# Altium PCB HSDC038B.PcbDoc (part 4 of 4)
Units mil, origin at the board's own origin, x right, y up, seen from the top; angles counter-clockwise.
Board outline 3620 x 4060 mil, 6 copper layers (Top Layer, Signal Layer 1, Signal Layer 2, Signal Layer 3, Signal Layer 4, Bottom Layer), stack 60.4 mil thick; 349 components, 209 nets, 1023 pads, 960 vias.
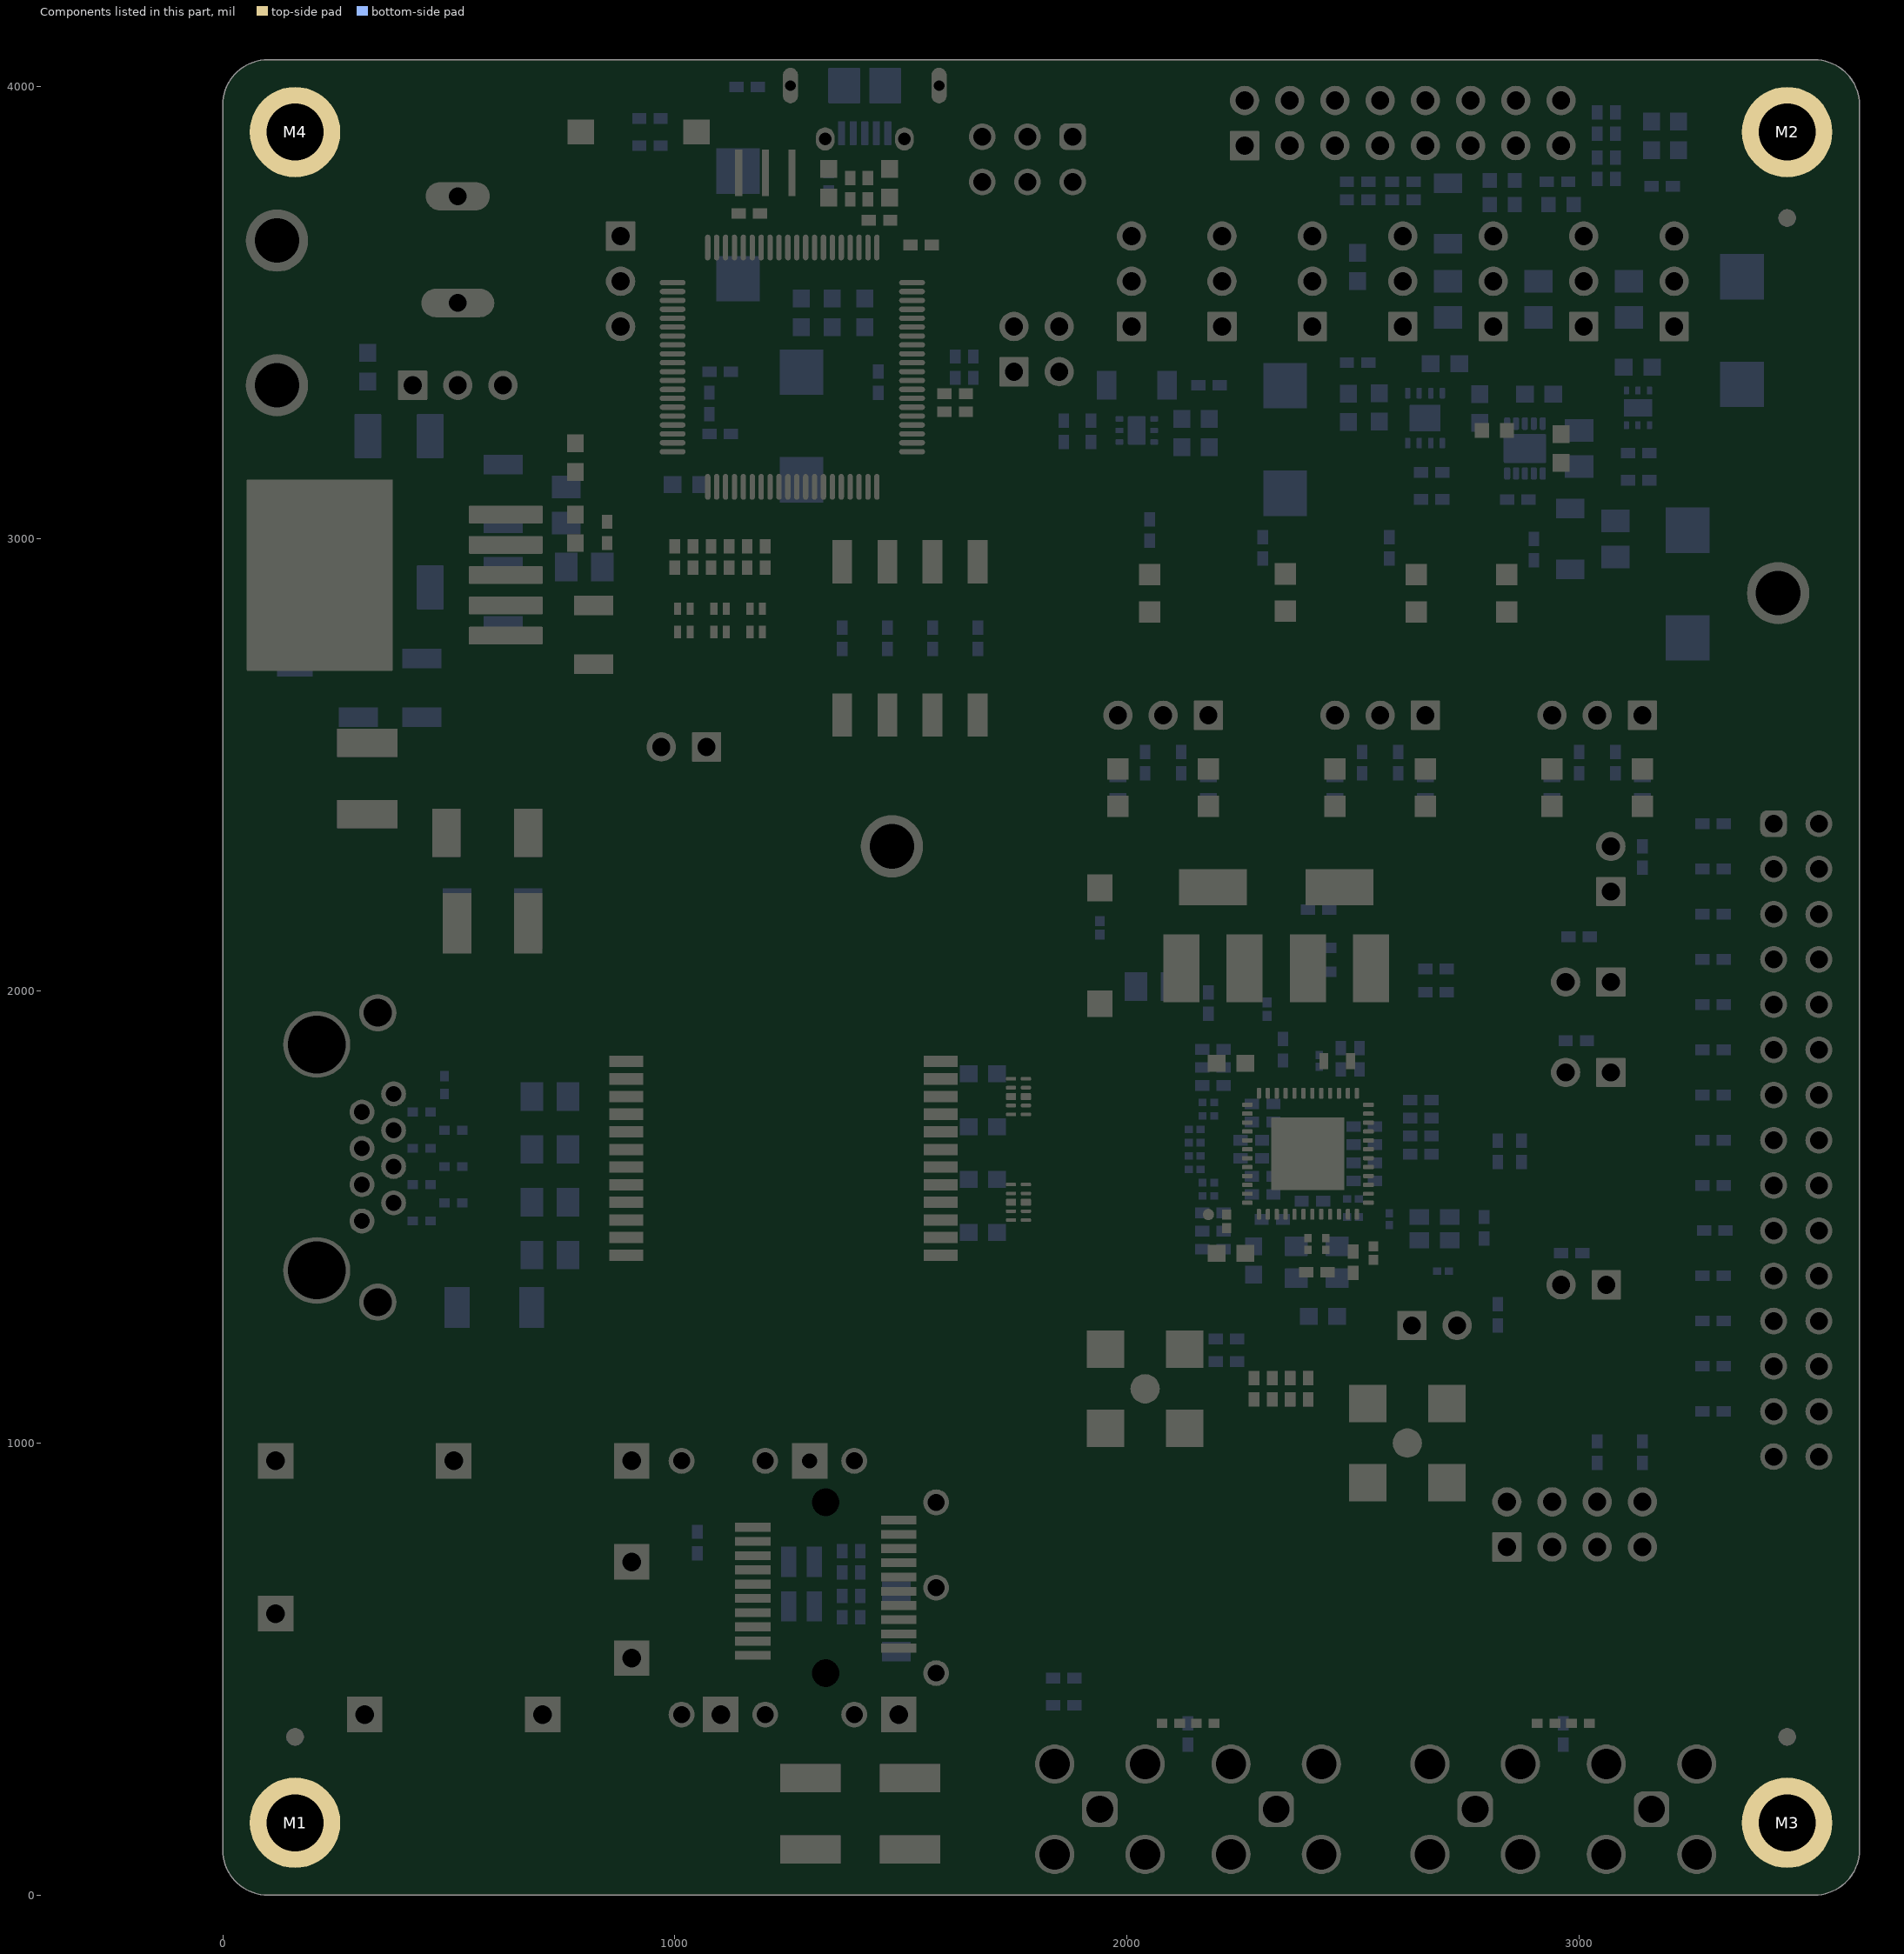
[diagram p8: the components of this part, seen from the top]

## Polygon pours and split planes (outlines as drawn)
EARTH_GND on Signal Layer 2 "Signal Layer 2-Earth GND" (solid, remove dead copper, pour order 84): 0,2420 550,2420 550,1900 830,1900 830,1355 550,1355 550,1000 940,1000 940,360 550,360 550,0 0,0
AUX_IOVDD on Signal Layer 2 "AUX_IOVDD_L03_P081" (solid, remove dead copper, pour order 81): 800,0 3620,0 3620,4060 2000,4060 2000,3340 3340,3340 3340,2920 3040,2920 2940,3020 2800,3020 2700,2920 1540,2920 1540,2460 900,2460 900,1980 1640,1980 1640,1280 900,1280 900,1180 1800,1180 1800,140 800,140
5V_SUPPLY on Signal Layer 2 "5V_SUPPLY_L03_P080" (solid, remove dead copper, pour order 80): 3320,2940 3320,3320 1440,3320 1040,3720 800,3720 800,3420 1040,3420 1520,2940 2700,2940 2800,3040 2940,3040 3040,2940
VFX on Signal Layer 2 "VFX_L03_P079" (solid, remove dead copper, pour order 79): 1520,2480 1520,2920 1040,3400 780,3400 780,3740 1040,3740 1440,3340 1980,3340 1980,4060 0,4060 0,2580 900,2580 900,2480
GND on Top Layer "Top Layer-GND Net" (solid, remove dead copper, pour order 77): 800,0 3620,0 3620,4060 0,4060 0,2580 900,2580 900,1980 1640,1980 1640,1280 900,1280 900,1180 1800,1180 1800,140 800,140
EARTH_GND on Top Layer "Top Layer- ERTH GND" (solid, remove dead copper, pour order 78): 0,2420 549.99,2420 549.99,1975 435,1975 245,1785 245,1480 370,1355 549.99,1355 549.99,1000 1600,1000 1600,230 549.99,230 549.99,0 0,0
5V_LDO on Top Layer "5V_LDO_L01_P076" (solid, remove dead copper, pour order 76): 540,3015 540,2960 870,2960 870,3015
EARTH_GND on Signal Layer 3 "Signal Layer 3-Earth GND" (solid, remove dead copper, pour order 94): 0,2420 549.96,2420 549.96,1900 830,1900 830,1355 549.96,1355 549.96,1000 940,1000 940,360 549.96,360 549.96,0 0,0
20V-5V on Signal Layer 3 "20V-5V_L04_P090" (solid, remove dead copper, pour order 90): 0,2580 900,2580 900,2480 1240,2480 1240,2660 960,2940 680,2940 680,4060 0,4060
5V_LDO on Signal Layer 3 "5V_LDO_L04_P085" (solid, remove dead copper, pour order 85): 700,2960 940,2960 940,3520 700,3520
MCU_VBUS on Signal Layer 3 "MCU_VBUS_L04_P086" (solid, remove dead copper, pour order 86): 2040,3620 2040,3000 2020,2980 1880,2980 1880,3140 1520,3500 1340,3500 1340,3620
MCU_VCC on Signal Layer 3 "MCU_VCC_L04_P089" (solid, remove dead copper, pour order 89): 2060,3620 2240,3620 2240,3020 2020,2800 1740,2800 1740,2680 1240,2680 960,2960 960,3540 700,3540 700,4060 1320,4060 1320,3480 1520,3480 1860,3140 1860,2960 2020,2960 2060,3000
FX3V3 on Signal Layer 3 "FX3V3_L04_P087" (solid, remove dead copper, pour order 87): 2260,3620 2440,3620 2440,3010 1900,2470 1900,1380 2260,1380 2260,0 800,0 800,140 1180,140 1180,330 1500,330 1500,140 1800,140 1800,930 1520,930 1520,800 1290,570 1230,570 1230,810 1370,810 1450,890 1450,1180 900,1180 900,1280 1640,1280 1640,1980 900,1980 900,2460 1260,2460 1260,2660 1760,2660 1760,2780 2020,2780 2260,3020
VDDA2P5 on Signal Layer 3 "VDDA2P5_L04_P091" (solid, remove dead copper, pour order 91): 2660,3620 2840,3620 2840,2630 2370,2160 2370,1840 2260,1730 2260,1680 2200,1680 2200,1620 2260,1620 2260,1460 2260,1400 2180,1400 2180,1420 2130,1460 2130,1780 2160,1810 2160,1860 2080,1940 2080,2240 2660,2820
VDDA1P8_EXT on Signal Layer 3 "VDDA1P8_EXT_L04_P088" (solid, remove dead copper, pour order 88): 2460,3760 2510,3810 2510,3920 2640,3920 2640,2820 2070,2250 2070,1940 2150,1860 2150,1810 2120,1780 2120,1460 2160,1420 2160,1400 1920,1400 1920,2470 2460,3010
VDDA1P0 on Signal Layer 3 "VDDA1P0_L04_P092" (solid, remove dead copper, pour order 92): 2860,3620 3040,3620 3040,2580 2510,2050 2510,1830 2600,1740 2600,1642 2312,1642 2300,1630 2210,1630 2210,1670 2270,1670 2270,1720 2380,1830 2380,2150 2860,2630
VDDIO on Signal Layer 3 "VDDIO_L04_P093" (solid, remove dead copper, pour order 93): 1340,4060 3620,4060 3620,0 2280,0 2280,1600 2280,1620 2300,1620 2318,1638 2610,1638 2610,1750 2520,1840 2520,2040 3060,2580 3060,3640 1340,3640
EARTH_GND on Signal Layer 1 "Signal Layer 1- ERTH GND" (solid, remove dead copper, pour order 82): 0,2420 550,2420 550,1900 830,1900 830,1355 550,1355 550,1000 1600,1000 1600,230 550,230 550,0 0,0
GND on Signal Layer 1 "Signal Layer 1-GND Net" (solid, remove dead copper, pour order 83): 800,0 3620,0 3620,4060 0,4060 0,2580 900,2580 900,1980 1640,1980 1640,1280 900,1280 900,1180 1800,1180 1800,140 800,140
GND on Bottom Layer "Bottom Layer-GND Net" (solid, remove dead copper, pour order 115): 800,0 3620,0 3620,4060 0,4060 0,2580 900,2580 900,1980 1640,1980 1640,1280 900,1280 900,1180 1800,1180 1800,140 800,140
VDDIO_DUT on Bottom Layer "VDDIO_DUT_L06_P114" (solid, remove dead copper, pour order 114): 3050,3510 3050,3430 3070,3410 3130,3410 3130,3310 3070,3310 2970,3410 2970,3510
VDDA1P0_DUT on Bottom Layer "VDDA1P0_DUT_L06_P113" (solid, remove dead copper, pour order 113): 2770,3510 2770,3430 2889.91,3310.09 2889.91,3240 2967.62,3240 2970,3237.62 2970,3375 2935.39,3409.61 2890.39,3409.61 2850,3450 2850,3510
5V_SUPPLY on Bottom Layer "5V_SUPPLY_L06_P112" (solid, remove dead copper, pour order 112): 2850,3080 2930,3000 3130,3000 3170,2960 3300,2960 3300,3080 3160,3080 3130,3110 3130,3270 3050,3270 3050,3200 2940,3200 2940,3160 2850,3160
VDDA_3V3_DUT on Bottom Layer "VDDA_3V3_DUT_L06_P111" (solid, remove dead copper, pour order 111): 2450,3510 2450,3420 2290,3420 2240,3370 2200,3370 2180,3350 2180,3330 2210,3300 2210,3240 2050.68,3240 2050.68,3510
VDDA2P5_DUT on Bottom Layer "VDDA2P5_DUT_L06_P110" (solid, remove dead copper, pour order 110): 2650,3510 2650,3300 2538,3300 2538,3348 2570,3380 2570,3510
NetC98_1 on Bottom Layer "NETC98_1_L06_P109" (solid, remove dead copper, pour order 109): 2300,3280 2510,3280 2510,3410 2300,3410
NetC110_1 on Bottom Layer "NETC110_1_L06_P108" (solid, remove dead copper, pour order 108): 2840,3810 2950,3810 2950,3540 2870,3540 2870,3680 2840,3710
EARTH_GND on Bottom Layer "Bottom Layer- ERTH GND" (solid, remove dead copper, pour order 116): 0,2420 549.99,2420 549.99,1975 435,1975 245,1785 245,1480 370,1355 549.99,1355 549.99,1000 1600,1000 1600,230 549.99,230 549.99,0 0,0
5V_SUPPLY on Bottom Layer "5V_SUPPLY_L06_P100" (solid, remove dead copper, pour order 100): 1845,3280 1845,3245 1995,3245 1995,3280
5V_SUPPLY on Bottom Layer "5V_SUPPLY_L06_P102" (solid, remove dead copper, pour order 102): 2670,3070 2670,3230 2610,3230 2610,3070
VDDA1P0 on Bottom Layer "VDDA1P0_L06_P098" (solid, remove dead copper, pour order 98): 2875,3520 2875,3435 2945,3435 2945,3520
NetJ32_6 on Bottom Layer "NETJ32_6_L06_P104" (solid, remove dead copper, pour order 104): 1605,4060 1605,3955 1540,3955 1540,3855 1485,3855 1485,3955 1355,3955 1355,3855 1305,3855 1305,3955 1165,3955 1165,4060
5V_LDO on Bottom Layer "5V_LDO_L06_P099" (solid, remove dead copper, pour order 99): 570,3065 570,2900 800,2900 800,2975 850,2975 850,3015 800,3065
VDDA1P8_EXT on Bottom Layer "VDDA1P8_EXT_L06_P097" (solid, remove dead copper, pour order 97): 2510,3910 2610,3910 2610,3730 2510,3730
VDDIO on Bottom Layer "VDDIO_L06_P103" (solid, remove dead copper, pour order 103): 3070,3520 3070,3430 3250,3430 3250,3520
VDDA2P5 on Bottom Layer "VDDA2P5_L06_P105" (solid, remove dead copper, pour order 105): 2675,3520 2675,3435 2745,3435 2745,3520
AUX_IOVDD_EXT on Bottom Layer "AUX_IOVDD_EXT_L06_P106" (solid, remove dead copper, pour order 106): 2920,3820 2920,3920 3100,3920 3100,3820
EARTH_GND on Signal Layer 4 "Signal Layer 1-Earth GND" (solid, remove dead copper, pour order 96): 0,2420 550,2420 550,1900 830,1900 830,1355 550,1355 550,1000 960,1000 960,360 550,360 550,0 0,0
GND on Signal Layer 4 "Signal Layer 1-GND Net" (solid, remove dead copper, pour order 95): 800,0 3620,0 3620,4060 0,4060 0,2580 900,2580 900,1980 1640,1980 1640,1280 900,1280 900,1180 1800,1180 1800,880 1730,810 1565,810 1545,830 1180,830 1180,720 1540,720 1560,740 1760,740 1760,620 1565,620 1535,650 1180,650 1180,530 1540,530 1560,550 1800,550 1800,140 800,140

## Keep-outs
Keep-Out Layer:
  lines w10: -5,100 ccw(c100,100) 100,-5 3520,-5 ccw(c3520,100) 3625,100 3625,3960 ccw(c3520,3960) 3520,4065 100,4065 ccw(c100,3960) -5,3960 -5,100

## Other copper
Top Layer:
  pour cut-out: 960,440 960,920 1560,920 1560,440
  pour cut-out: 2280,1760 2280,1520 2520,1520 2520,1760
  text ".Layer_Name" at 680,-867.49 h60
Signal Layer 1:
  pour cut-out: 960,440 960,920 1560,920 1560,440
  text ".Layer_Name" at 680,-867.49 h60
Signal Layer 2:
  text ".Layer_Name" at 680,-867.49 h60
Signal Layer 3:
  text ".Layer_Name" at 680,-867.49 h60
Signal Layer 4:
  text ".Layer_Name" at 680,-867.49 h60
Bottom Layer:
  pour cut-out: 960,440 960,920 1560,920 1560,440
  text ".Layer_Name" at 758,-867.49 h60

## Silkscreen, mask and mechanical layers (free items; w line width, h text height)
Top Overlay:
  circle w10: c2230,1770 r5
  lines w7: 1950,3535 1950,3520 1960,3520 ; 1950,3545 1950,3555 ; 1950,3565 1950,3575 ; 1950,3585 1950,3595 ; 1950,3605 1950,3615 ; 1950,3625 1950,3635 ; 1950,3645 1950,3655 ; 1950,3665 1950,3675 ; 1950,3685 1950,3695 ; 1950,3705 1950,3720 1960,3720 ; 2150,3535 2150,3520 2160,3520 ; 2150,3545 2150,3555 ; 2150,3565 2150,3575 ; 2150,3585 2150,3595 ; 2150,3605 2150,3615 ; 2150,3625 2150,3635 ; 2150,3645 2150,3655 ; 2150,3665 2150,3675 ; 2150,3685 2150,3695 ; 2150,3705 2150,3720 2160,3720 ; 2350,3535 2350,3520 2360,3520 ; 2350,3545 2350,3555 ; 2350,3565 2350,3575 ; 2350,3585 2350,3595 ; 2350,3605 2350,3615 ; 2350,3625 2350,3635 ; 2350,3645 2350,3655 ; 2350,3665 2350,3675 ; 2350,3685 2350,3695 ; 2350,3705 2350,3720 2360,3720 ; 2550,3535 2550,3520 2560,3520 ; 2550,3545 2550,3555 ; 2550,3565 2550,3575 ; 2550,3585 2550,3595 ; 2550,3605 2550,3615 ; 2550,3625 2550,3635 ; 2550,3645 2550,3655 ; 2550,3665 2550,3675 ; 2550,3685 2550,3695 ; 2550,3705 2550,3720 2560,3720 ; 2750,3535 2750,3520 2760,3520 ; 2750,3545 2750,3555 ; 2750,3565 2750,3575 ; 2750,3585 2750,3595 ; 2750,3605 2750,3615 ; 2750,3625 2750,3635 ; 2750,3645 2750,3655 ; 2750,3665 2750,3675 ; 2750,3685 2750,3695 ; 2750,3705 2750,3720 2760,3720 ; 2950,3535 2950,3520 2960,3520 ; 2950,3545 2950,3555 ; 2950,3565 2950,3575 ; 2950,3585 2950,3595 ; 2950,3605 2950,3615 ; 2950,3625 2950,3635 ; 2950,3645 2950,3655 ; 2950,3665 2950,3675 ; 2950,3685 2950,3695 ; 2950,3705 2950,3720 2960,3720 ; 3150,3535 3150,3520 3160,3520 ; 3150,3545 3150,3555 ; 3150,3565 3150,3575 ; 3150,3585 3150,3595 ; 3150,3605 3150,3615 ; 3150,3625 3150,3635 ; 3150,3645 3150,3655 ; 3150,3665 3150,3675 ; 3150,3685 3150,3695 ; 3150,3705 3150,3720 3160,3720 ; 3260,3420 3270,3420 3270,3435 ; 3260,3620 3270,3620 3270,3605 ; 3270,3445 3270,3455 ; 3270,3465 3270,3475 ; 3270,3485 3270,3495 ; 3270,3505 3270,3515 ; 3270,3525 3270,3535 ; 3270,3545 3270,3555 ; 3270,3565 3270,3575 ; 3270,3585 3270,3595
  text "RESET" at 860,4000 h25
  text "GND" at 2110,3957.5 h25
  text "USB2MDIO" at 1270.05,3916.83 h40
  text "GND" at 1942,3877.5 h25
  text "5V-USB" at 809.19,3740 h25
  text "MCU_VBUS_EXT" at 3055,3737.54 h25 r90
  text "MCU_VCC_EXT" at 3095,3737.54 h25 r90
  text "FX3V3_EXT" at 3135,3737.5 h25 r90
  text "VDDA2P5_EXT" at 3215,3737.53 h25 r90
  text "VDDA1P0_EXT" at 3255,3737.54 h25 r90
  text "VDDIO_EXT" at 3295,3737.54 h25 r90
  text "AUX_IOVDD_EXT" at 3335,3737.53 h25 r90
  text "VDDA1P8_EXT" at 3175,3737.5 h25 r90
  text "MDC" at 1695,3664.32 h25 r90
  text "VFX" at 1901,3644.99 h25 r90
  text "MDIO" at 1801,3620 h25 r90
  text "PCB" at 730,3557.5 h25
  text "GND" at 1760,3540 h25
  text "SUPPLY" at 12.87,3470 h30
  text "ASM" at 480.68,3423.01 h25
  text "MCU_VBUS_EXT" at 1955,3400 h25 r90
  text "MCU_VCC_EXT" at 2155,3400 h25 r90
  text "FX3V3_EXT" at 2355,3400 h25 r90
  text "VDDA2P5_EXT" at 2555,3400 h25 r90
  text "VDDA1P0_EXT" at 2755,3400 h25 r90
  text "VDDIO_EXT" at 2955,3400 h25 r90
  text "5V-LDO" at 809.19,3360 h25
  text "AUX_IOVDD_EXT" at 3155,3360 h25 r90
  text "OFF" at 386.68,3240 h25
  text "U6" at 499.17,3240 h25
  text "ON" at 599.17,3240 h25
  text "TST" at 1765,3218 h25 r90
  text "RST" at 1865,3218 h25 r90
  text "Onboard Power for:" at 3460,3180 h25 r90
  text "20V MAX" at -4.63,3150 h30
  text "VDDA2P5" at 2612.5,2947.53 h25 r90
  text "PU" at 1780,2940 h25
  text "5V_SUPPLY" at 2010.41,2927.52 h25 r90
  text "FX3V3" at 2312.5,2927.5 h25 r90
  text "VDDIO" at 2910.41,2927.53 h25 r90
  text "LINK" at 2027.52,2690 h30
  text "1000BT LINK" at 2405.05,2690 h30
  text "ACTIVITY" at 2930.04,2690 h30
  text "PD" at 1780,2600 h25
  text "GND" at 3550,2440 h25 r90
  text "LED_1" at 2572.5,2400 h30 r90
  text "LED_0" at 2092.5,2390 h30 r90
  text "LED_2" at 3052.5,2390 h30 r90
  text "VFX" at 1085,2388 h25 r90
  text "PWDN" at 3210,2350 h30
  text "20V-5V" at 985,2308 h25 r90
  text "MIRROR_EN" at 2820,2250 h20
  text "RESET" at 3210,2250 h30
  text "RXCTRL" at 3210,2150 h30
  text "TXCTRL" at 3210,2050 h30
  text "RESET" at 1840,2040 h25 r90
  text "'.PRJ_Number''.PCB_Rev'" at 940,2020 h40
  text "OP_MD [1]" at 2720,1980 h20
  text "RXD3" at 3210,1950 h30
  text "TXD3" at 3210,1850 h30
  text "OP_MD [2]" at 2710,1780 h20
  text "RXD2" at 3210,1750 h30
  text "TXD2" at 3210,1650 h30
  text "RXD1" at 3220,1550 h30
  text "TXD1" at 3220,1450 h30
  text "LNK_LOSS" at 2910,1430 h20
  text "RXD0" at 3210,1350 h30
  text "OP_MD [0]" at 2570,1300 h20
  text "TXD0" at 3210,1250 h30
  text "RXCLK" at 3210,1150 h30
  text "GTXCLK" at 3210,1050 h30
  text "JTAG_CLK" at 2865,940 h25 r90
  text "JTAG_TDO_OUT" at 2965,940 h25 r90
  text "JTAG_TMS" at 3065,940 h25 r90
  text "JTAG_TDI" at 3165,940 h25 r90
  text "GND" at 3220,745 h25
  text "SI_P" at 2693.02,360 h35
  text "SI_N" at 3083.02,360 h35
  text "SO_N" at 1840,350 h35
  text "SO_P" at 2260,345.16 h35
  text ".Layer_Name" at 664,-867.49 h60
Bottom Overlay:
  text ".Layer_Name" at 680,-867.49 h60
Top Paste:
  text ".Layer_Name" at 577,-867.49 h60
Bottom Paste:
  text ".Layer_Name" at 577,-887.49 h60
Top Solder:
  text ".Layer_Name" at 577,-867.49 h60
  text ".Layer_Name" at 577,-867.49 h60
Bottom Solder:
  lines w10: 2323.62,1590 2329.13,1595.51
  text ".Layer_Name" at 577,-887.49 h60
M1 Board Outline:
  the board outline again, w10
  text ".Layer_Name" at 577,-887.49 h60
M2 Board Dimensions:
  rectangle: 0,-284 125,-159
  rectangle: 125,-409 500,-284
  lines w7: 0,-284 1000,-284 ; 125,-409 125,-159 ; 250,-409 250,-159 ; 500,-409 500,-159 ; 750,-409 750,-159 ; 0,-409 1000,-409 1000,-159 0,-159 0,-409
  text "Radius 100mil x 4 locations" at 3640,4080 h72.83
  text ".Layer_Name" at 577,-887.49 h60
M3 3D STEP Top:
  text ".Layer_Name" at 577,-867.49 h60
M4 3D STEP Bottom:
  text ".Layer_Name" at 577,-887.49 h60
M5 Assembly Top:
  lines w10: -292,-939.17 6308,-939.17 ; -292,-735.83 6310,-735.83 ; -292,-532.5 -292,-1142.5 3713,-1142.5 6310,-1142.5 6310,-532.5 -291.5,-532.5 -291.5,-1142.5 1284,-1142.5 ; 2173,-1142.5 2173,-532.5 ; 3440,-735.83 3440,-532.5 ; 4280,-735.83 4280,-532.5 ; 4902,-1149 4902,-946.17
  text "COMPONENTS MARKED 'DNP' SHOULD NOT BE POPULATED." at 1153.5,-327.5 h60
  text "ASSEMBLY VARIANT:" at 1153,-443 h60
  text ".VariantName" at 2189,-443 h60
  text "PCB VIEWED FROM TOP SIDE" at -228.5,-664.67 h60
  text "BOARD #:" at 2248,-664.67 h60
  text ".PRJ_Number" at 2793.5,-664.67 h60
  text "REV:" at 3638,-664.67 h60
  text ".PCB_Rev" at 3929.5,-664.67 h60
  text "SVN REV:" at 4476,-664.67 h60
  text ".VersionControl_RevNumber" at 4982,-664.67 h60
  text ".Layer_Name" at 680,-867.49 h60
  text "TID #:" at 2248,-868 h60
  text ".TID" at 2793.5,-868 h60
  text "PLOT NAME =" at -228.5,-1073.34 h60
  text ".plot_File_Name" at 577,-1073.34 h60
  text "GENERATED    :" at 2250,-1073.34 h60
  text ".Print_Date" at 3119.5,-1073.34 h60
  text ".Print_Time" at 3848.5,-1073.34 h60
  text "TEXAS INSTRUMENTS" at 5113,-1073.34 h60
M6 Assembly Bottom:
  lines w10: -292.5,-736.33 6309.5,-736.33 ; -290.5,-939.67 6309.5,-939.67 ; 1115.5,-1149.5 1115.5,-946.67 ; 1737.5,-736.33 1737.5,-533 ; 2577.5,-736.33 2577.5,-533 ; 3844.5,-1143 3844.5,-533 ; 4733.5,-1143 6309,-1143 6309,-533 -292.5,-533 -292.5,-1143 2304.5,-1143 6309.5,-1143 6309.5,-533
  text "COMPONENTS MARKED 'DNP' SHOULD NOT BE POPULATED." at 6102,-327 h60
  text ".VariantName" at 5058,-443 h60
  text "ASSEMBLY VARIANT:" at 6097,-443 h60
  text ".VersionControl_RevNumber" at 1035.5,-665.17 h60
  text "SVN REV:" at 1541.5,-665.17 h60
  text ".PCB_Rev" at 2088,-665.17 h60
  text "REV:" at 2379.5,-665.17 h60
  text ".PRJ_Number" at 3224,-665.17 h60
  text "BOARD #:" at 3769.5,-665.17 h60
  text "PCB VIEWED FROM BOTTOM SIDE" at 6246,-665.17 h60
  text ".Layer_Name" at 680,-867.49 h60
  text ".TID" at 3224,-868.5 h60
  text "TID #:" at 3769.5,-868.5 h60
  text "TEXAS INSTRUMENTS" at 904.5,-1073.84 h60
  text ".Print_Time" at 2169,-1073.84 h60
  text ".Print_Date" at 2898,-1073.84 h60
  text "GENERATED    :" at 3767.5,-1073.84 h60
  text ".plot_File_Name" at 5440.5,-1073.84 h60
  text "PLOT NAME =" at 6246,-1073.84 h60
M7 LPKF Text Top:
  text ".Layer_Name" at 680,-867.49 h60
M8 LPKF Text Bottom:
  text ".Layer_Name" at 680,-867.49 h60
M9 Title Sheet:
  drawing of 57 lines, arcs and shapes, not listed
  text "1" at 739.84,8027.5 h70
  text "2" at 3235.5,8027.5 h70
  text "3" at 5724.84,8027.5 h70
  text "4" at 8231.51,8027.5 h70
  text "5" at 10730.5,8027.5 h70
  text "6" at 13235.5,8027.5 h70
  text "A" at -416.5,6884.5 h70
  text "A" at 14383.5,6884.5 h70
  text "B" at -416.5,4504.5 h70
  text "B" at 14383.5,4504.5 h70
  text "C" at -416.5,2129.5 h70
  text "C" at 14383.5,2129.5 h70
  text "PROJECT TITLE:" at 11343.5,268.5 h45
  text ".PRJ_Title" at 11393.5,135.17 h70
  text "DESIGNED FOR:" at 11343.5,-32.5 h45
  text ".PRJ_Customer" at 11393.5,-172.5 h70
  text "D" at -416.5,-240.5 h70
  text "D" at 14383.5,-240.5 h70
  text "FILE NAME:" at 11343.5,-332.5 h45
  text ".PCB_File_Name_No_Path" at 11393.5,-452.5 h70
  text "Texas Instruments (TI) and/or its licensors do not warrant the accuracy or completeness of this specification" at 6374,-614.34 h45
  text "ENGINEER:" at 11343.5,-622.5 h45
  text "LAYOUT BY:" at 12848.5,-622.5 h45
  text "or any information contained therein. TI and/or its licensors do not warrant that this design will meet" at 6329.01,-727 h45
  text ".PRJ_Engineer" at 11393.5,-777.49 h70
  text ".PCB_Layout" at 12899,-777.49 h70
  text "the specifications, will be suitable for your application or fit for any particular purpose, or will operate in" at 6329.01,-839.67 h45
  text "ALTIUM DESIGNER VERSION:" at 12848.5,-932.5 h45
  text "an implementation. TI and/or its licensors do not warrant that the design is production worthy. You should" at 6329.01,-952.33 h45
  text "completely validate and test your design implementation to confirm the system functionality for your application." at 6374,-1065 h45
  text ".print_Scale" at 11393.5,-1065.83 h70
  text ".Application_BuildNumber" at 12899,-1065.83 h70
  text "1" at 739.84,-1272.5 h70
  text "2" at 3235.5,-1272.5 h70
  text "3" at 5724.84,-1272.5 h70
  text "4" at 8231.51,-1272.5 h70
  text "5" at 10730.5,-1272.5 h70
  text "6" at 13235.5,-1272.5 h70
M10 Fab Notes:
  drawing of 185 lines, arcs and shapes, not listed
  text "DESIGN INFORMATION" at 12381.02,5901 h60
  text "MIN. TRACK WIDTH:" at 11736.46,5721 h60
  text "6" at 12832.7,5721 h60
  text "MIL" at 12987.46,5721 h60
  text "MIN. CLEARANCE:" at 11736.46,5589 h60
  text "5" at 12830.7,5589 h60
  text "MIL" at 12987.46,5589 h60
  text "MIN. VIA PAD SIZE:" at 11736.46,5457 h60
  text "17.874" at 12619.71,5457 h60
  text "MIL" at 12987.46,5457 h60
  text "0.127mm (5MIL)" at 12431.46,5315.29 h60
  text "MINIMUM ANNULAR RING" at 11407.23,5311 h60
  text "EXTERNAL" at 13139.46,5311 h60
  text "PER" at 11607.23,5193 h60
  text "IPC-D-275 CLASS 2 LEVEL C" at 11827.23,5193 h60
  text "MIL, HOLES" at 13315.46,5080.71 h60
  text "+/-" at 12923,5080 h60
  text "+/-" at 13777,5080 h60
  text "REGISTRATION TOLERANCES:" at 11407.23,5075 h60
  text "METAL" at 12607,5075 h60
  text "5" at 13183.2,5075 h60
  text "3" at 14016.2,5075 h60
  text "MIL" at 14132.46,5075 h60
  text "MATERIAL:" at 11332.46,4865.54 h60
  text "FR-4 High Tg" at 12318.9,4725.21 h60
  text "FR-408" at 11753.46,4716.64 h60
  text "X" at 12165.46,4716.64 h60
  text "OTHER" at 13241.46,4716.64 h60
  text "62 MIL (1.6mm) +/-10%" at 12073.56,4553.92 h60
  text "THICKNESS:" at 11407.23,4549.64 h60
  text "X" at 11945.4,4549.64 h60
  text "OTHER" at 13358.46,4549.64 h60
  text "TOLERANCE:" at 11407.23,4391.64 h60
  text "X" at 12246.53,4391.64 h60
  text "ANSI IPC-6012 TYPE 3 CLASS 2" at 12433.48,4391.64 h60
  text "OTHER +/-" at 12433.46,4235.64 h60
  text "BOW & TWIST:" at 11407.23,4078.64 h60
  text "X" at 12246.53,4078.64 h60
  text "ANSI IPC-6012 TYPE 3 CLASS 2" at 12433.48,4078.64 h60
  text "OTHER +/-" at 12433.46,3920.13 h60
  text "DRILLING:" at 11332.46,3781.64 h60
  text "REFERENCE:" at 11407.23,3664.64 h60
  text "X" at 12055.46,3664.64 h60
  text "AS SHOWN" at 12242.46,3664.64 h60
  text "X" at 12956.46,3664.64 h60
  text "NC_DRILL FILES" at 13093.46,3664.64 h60
  text "PTH MIN COPPER THICKNESS:" at 11407.23,3506.64 h60
  text "X" at 12757.46,3506.64 h60
  text "1MIL" at 12894.46,3506.64 h60
  text "OTHER" at 13391.46,3506.64 h60
  text "BOARD FINISH:" at 11332.46,3347.64 h60
  text "SILKSCREEN:" at 11487.68,3229.64 h60
  text "X" at 12436.46,3229.64 h60
  text "TOP" at 12562.46,3229.64 h60
  text "X" at 12946.46,3229.64 h60
  text "BOTTOM" at 13073.46,3229.64 h60
  text "SILKSCREEN COLOR:" at 11487.68,3062.64 h60
  text "X" at 12435.42,3062.64 h60
  text "WHITE" at 12562.46,3062.64 h60
  text "OTHER" at 13073.46,3062.64 h60
  text "SOLDER RESIST COLOR:" at 11487.68,2892.64 h60
  text "X" at 12055.42,2733.44 h60
  text "GREEN" at 12182.46,2733.44 h60
  text "BLUE" at 12773.46,2733.44 h60
  text "OTHER" at 13311.46,2733.44 h60
  text "IMMERSION GOLD (ENIG)" at 12393.46,2544.92 h60
  text "ENEPIG" at 13731,2541.64 h60
  text "SURFACE FINISH:" at 11332.46,2540.64 h60
  text "X" at 12206.51,2540.64 h60
  text "IMM. TIN/SILVER OR EQUIV" at 11662,2383.64 h60
  text "OTHER" at 13093.46,2383.64 h60
  text "ARRAY/PANEL:" at 11332.46,2204.64 h60
  text "CUT AND TRIM PER MECH LAYER 1" at 12393.46,2200.35 h60
  text "N.C. ROUTE" at 12393.46,2048.64 h60
  text "X" at 13072.46,2048.64 h60
  text "V. SCORE" at 13259.46,2048.64 h60
  text "CERTIFICATION:" at 11332.46,1911.64 h60
  text "MATERIALS AND WORKMANSHIP FOR ALL PCBS" at 12057.46,1911.64 h60
  text "TO MEET OR EXCEED THE REQUIREMENTS OF:" at 12057.46,1813.64 h60
  text "X" at 11683.96,1677.13 h60
  text "ANSI IPC-A-600F CLASS ->" at 11822.96,1677.13 h60
  text "X" at 13462.02,1677.13 h60
  text "2" at 13580.96,1677.14 h60
  text "1" at 13265.96,1675.64 h60
  text "3" at 13934.96,1675.64 h60
  text "X" at 11686.02,1517.64 h60
  text "UL 94V-0" at 11822.96,1517.64 h60
  text "X" at 12498.02,1517.64 h60
  text "RoHS" at 12634.96,1517.64 h60
  text "OTHER" at 13279.36,1517.64 h60
  text "PER ORDER" at 13676.42,1517.64 h60
  text "ADDITIONAL REQUIREMENTS:" at 11332.46,1376.64 h60
  text "MICROSECTION:" at 11407.23,1261.64 h60
  text "YES" at 12312.96,1261.64 h60
  text "REQUIRED" at 13174.46,1105.49 h60
  text "BARE BOARD ELEC. TEST:" at 11407.23,1102.64 h60
  text "NONE" at 12712.96,1102.64 h60
  text "X" at 13047.46,1102.64 h60
  text "PER ORDER" at 13766.46,1102.64 h60
  text "MANUFACTURER'S UL:" at 11407.23,945.64 h60
  text "RAIL" at 12572.96,941.35 h60
  text "METAL" at 13064.77,941.35 h60
  text "X" at 13440,941 h60
  text "SILK" at 13576.46,941.35 h60
  text "Impedance Control:" at 8128,624 h60
  text "Differential Controlled to 100 Ohms (+/-10%)" at 8413,486 h60
  text "All 6 mil traces with 12 mil spacing on Layers 1 and 6" at 8738,336 h60
  text "All 6 mil traces with 11 mil spacing on Layer 3" at 8738,196 h60
  text "Single Ended Controlled to 50 Ohms (+/-10%)" at 8416,-55 h60
  text "All 8 mil traces on Layers 1, 3, and 6" at 8738,-252 h60
  text ".Layer_Name" at 567,-897.49 h60
M11 Gerber Information:
  lines w10: -292,-939.17 6308,-939.17 ; -292,-735.83 6310,-735.83 ; -292,-532.5 -292,-1142.5 3713,-1142.5 6310,-1142.5 6310,-532.5 -291.5,-532.5 -291.5,-1142.5 1284,-1142.5 ; 2173,-1142.5 2173,-532.5 ; 3440,-735.83 3440,-532.5 ; 4280,-735.83 4280,-532.5 ; 4902,-1149 4902,-946.17
  text "ALL ARTWORK VIEWED FROM TOP SIDE" at -228.5,-664.67 h60
  text "BOARD #:" at 2248,-664.67 h60
  text ".PRJ_Number" at 2793.5,-664.67 h60
  text "REV:" at 3638,-664.67 h60
  text ".PCB_Rev" at 3929.5,-664.67 h60
  text "SVN REV:" at 4476,-664.67 h60
  text ".VersionControl_RevNumber" at 4982,-664.67 h60
  text "LAYER NAME =" at -228.5,-867.49 h60
  text "TID #:" at 2248,-868 h60
  text ".TID" at 2793.5,-868 h60
  text "PLOT NAME =" at -228.5,-1073.34 h60
  text ".plot_File_Name" at 577,-1073.34 h60
  text "GENERATED    :" at 2250,-1073.34 h60
  text ".Print_Date" at 3119.5,-1073.34 h60
  text ".Print_Time" at 3848.5,-1073.34 h60
  text "TEXAS INSTRUMENTS" at 5113,-1073.34 h60
M12 Stackup:
  drawing of 399 lines, arcs and shapes, not listed
  text "Layer" at 6457.5,7697.5 h60
  text "Name" at 6867.41,7697.5 h60
  text "Material" at 7807.15,7697.5 h60
  text "Thickness" at 8666.92,7697.5 h60
  text "Constant" at 9316.76,7697.5 h60
  text "Board Layer Stack" at 9886.62,7697.5 h60
  text "1" at 6457.5,7577.5 h60
  text "Top Overlay" at 6867.41,7577.5 h60
  text "2" at 6457.5,7457.5 h60
  text "Top Solder" at 6867.41,7457.5 h60
  text "Solder Resist" at 7807.15,7457.5 h60
  text "0.70mil" at 8666.92,7457.5 h60
  text "3.5" at 9316.76,7457.5 h60
  text "3" at 6457.5,7337.5 h60
  text "Top Layer" at 6867.41,7337.5 h60
  text "Copper" at 7807.15,7337.5 h60
  text "1.40mil" at 8666.92,7337.5 h60
  text "4" at 6457.5,7217.5 h60
  text "Dielectric 1" at 6867.41,7217.5 h60
  text "FR-4" at 7807.15,7217.5 h60
  text "5.00mil" at 8666.92,7217.5 h60
  text "4.6" at 9316.76,7217.5 h60
  text "5" at 6457.5,7097.5 h60
  text "Signal Layer 1" at 6867.41,7097.5 h60
  text "Copper" at 7807.15,7097.5 h60
  text "1.40mil" at 8666.92,7097.5 h60
  text "6" at 6457.5,6977.5 h60
  text "Dielectric  2" at 6867.41,6977.5 h60
  text "FR-4" at 7807.15,6977.5 h60
  text "5.00mil" at 8666.92,6977.5 h60
  text "4.6" at 9316.76,6977.5 h60
  text "7" at 6457.5,6857.5 h60
  text "Signal Layer 2" at 6867.41,6857.5 h60
  text "Copper" at 7807.15,6857.5 h60
  text "1.40mil" at 8666.92,6857.5 h60
  text "8" at 6457.5,6737.5 h60
  text "Dielectric 3" at 6867.41,6737.5 h60
  text "FR-4" at 7807.15,6737.5 h60
  text "32.00mil" at 8666.92,6737.5 h60
  text "4.6" at 9316.76,6737.5 h60
  text "9" at 6457.5,6617.5 h60
  text "Signal Layer 3" at 6867.41,6617.5 h60
  text "Copper" at 7807.15,6617.5 h60
  text "1.40mil" at 8666.92,6617.5 h60
  text "10" at 6457.5,6497.5 h60
  text "Dielectric 4" at 6867.41,6497.5 h60
  text "FR-4" at 7807.15,6497.5 h60
  text "5.00mil" at 8666.92,6497.5 h60
  text "4.6" at 9316.76,6497.5 h60
  text "11" at 6457.5,6377.5 h60
  text "Signal Layer 4" at 6867.41,6377.5 h60
  text "Copper" at 7807.15,6377.5 h60
  text "1.40mil" at 8666.92,6377.5 h60
  text "12" at 6457.5,6257.5 h60
  text "Dielectric 5" at 6867.41,6257.5 h60
  text "FR-4" at 7807.15,6257.5 h60
  text "5.00mil" at 8666.92,6257.5 h60
  text "4.6" at 9316.76,6257.5 h60
  text "13" at 6457.5,6137.5 h60
  text "Bottom Layer" at 6867.41,6137.5 h60
  text "Copper" at 7807.15,6137.5 h60
  text "1.40mil" at 8666.92,6137.5 h60
  text "14" at 6457.5,6017.5 h60
  text "Bottom Solder" at 6867.41,6017.5 h60
  text "Solder Resist" at 7807.15,6017.5 h60
  text "0.70mil" at 8666.92,6017.5 h60
  text "3.5" at 9316.76,6017.5 h60
  text "15" at 6457.5,5897.5 h60
  text "Bottom Overlay" at 6867.41,5897.5 h60
  text ".Layer_Name" at 567,-887.49 h60
M13 Component Bodies Top:
  text ".Layer_Name" at 577,-867.49 h60
M14 Component Bodies Bottom:
  text ".Layer_Name" at 577,-867.49 h60
M15 Courtyards Top:
  text ".Layer_Name" at 577,-867.49 h60
M16 Courtyards Bottom:
  text ".Layer_Name" at 577,-867.49 h60
Drill Drawing:
  drawing of 182 lines, arcs and shapes, not listed
  text "Symbol" at 7990.88,5650.18 h72
  text "Quantity" at 8291.32,5650.18 h72
  text "Finished Hole Size" at 8623.14,5650.18 h72
  text "Plated" at 9259.24,5650.18 h72
  text "Hole Type" at 9518.24,5650.18 h72
  text "2" at 8291.32,5525.84 h60
  text "61.02mil (1.550mm)" at 8623.14,5525.84 h60
  text "NPTH" at 9259.24,5525.84 h60
  text "Round" at 9518.24,5525.84 h60
  text "91" at 8291.32,5401.51 h60
  text "7.87mil (0.200mm)" at 8623.14,5401.51 h60
  text "PTH" at 9259.24,5401.51 h60
  text "Round" at 9518.24,5401.51 h60
  text "K" at 7965.59,5391.51 h55.26
  text "13" at 8291.32,5277.17 h60
  text "8.00mil (0.203mm)" at 8623.14,5277.17 h60
  text "PTH" at 9259.24,5277.17 h60
  text "Round" at 9518.24,5277.17 h60
  text "113" at 8291.32,5152.83 h60
  text "10.00mil (0.254mm)" at 8623.14,5152.83 h60
  text "PTH" at 9259.24,5152.83 h60
  text "Round" at 9518.24,5152.83 h60
  text "728" at 8291.32,5028.5 h60
  text "12.00mil (0.305mm)" at 8623.14,5028.5 h60
  text "PTH" at 9259.24,5028.5 h60
  text "Round" at 9518.24,5028.5 h60
  text "G" at 7965.59,5018.51 h55.26
  text "15" at 8291.32,4904.16 h60
  text "16.00mil (0.406mm)" at 8623.14,4904.16 h60
  text "PTH" at 9259.24,4904.16 h60
  text "Round" at 9518.24,4904.16 h60
  text "F" at 7965.59,4894.17 h55.26
  text "1" at 8291.32,4779.83 h60
  text "33.47mil (0.850mm)" at 8623.14,4779.83 h60
  text "PTH" at 9259.24,4779.83 h60
  text "Round" at 9518.24,4779.83 h60
  text "8" at 8291.32,4655.49 h60
  text "35.04mil (0.890mm)" at 8623.14,4655.49 h60
  text "PTH" at 9259.24,4655.49 h60
  text "Round" at 9518.24,4655.49 h60
  text "C" at 7965.59,4645.5 h55.26
  text "9" at 8291.32,4531.16 h60
  text "37.40mil (0.950mm)" at 8623.14,4531.16 h60
  text "PTH" at 9259.24,4531.16 h60
  text "Round" at 9518.24,4531.16 h60
  text "30" at 8291.32,4406.82 h60
  text "39.37mil (1.000mm)" at 8623.14,4406.82 h60
  text "PTH" at 9259.24,4406.82 h60
  text "Round" at 9518.24,4406.82 h60
  text "6" at 8291.32,4282.49 h60
  text "39.37mil (1.000mm)" at 8623.14,4282.49 h60
  text "PTH" at 9259.24,4282.49 h60
  text "Round" at 9518.24,4282.49 h60
  text "76" at 8291.32,4158.15 h60
  text "40.00mil (1.016mm)" at 8623.14,4158.15 h60
  text "PTH" at 9259.24,4158.15 h60
  text "Round" at 9518.24,4158.15 h60
  text "10" at 8291.32,4033.82 h60
  text "41.34mil (1.050mm)" at 8623.14,4033.82 h60
  text "PTH" at 9259.24,4033.82 h60
  text "Round" at 9518.24,4033.82 h60
  text "4" at 8291.32,3909.48 h60
  text "59.06mil (1.500mm)" at 8623.14,3909.48 h60
  text "PTH" at 9259.24,3909.48 h60
  text "Round" at 9518.24,3909.48 h60
  text "D" at 7965.59,3899.49 h55.26
  text "2" at 8291.32,3785.15 h60
  text "61.81mil (1.570mm)" at 8623.14,3785.15 h60
  text "PTH" at 9259.24,3785.15 h60
  text "Round" at 9518.24,3785.15 h60
  text "A" at 7965.59,3775.16 h55.26
  text "16" at 8291.32,3660.81 h60
  text "66.93mil (1.700mm)" at 8623.14,3660.81 h60
  text "PTH" at 9259.24,3660.81 h60
  text "Round" at 9518.24,3660.81 h60
  text "4" at 8291.32,3536.48 h60
  text "98.43mil (2.500mm)" at 8623.14,3536.48 h60
  text "PTH" at 9259.24,3536.48 h60
  text "Round" at 9518.24,3536.48 h60
  text "E" at 7965.59,3526.49 h55.26
  text "4" at 8291.32,3412.14 h60
  text "126.00mil (3.200mm)" at 8623.14,3412.14 h60
  text "PTH" at 9259.24,3412.14 h60
  text "Round" at 9518.24,3412.14 h60
  text "2" at 8291.32,3287.81 h60
  text "128.00mil (3.251mm)" at 8623.14,3287.81 h60
  text "PTH" at 9259.24,3287.81 h60
  text "Round" at 9518.24,3287.81 h60
  text "B" at 7965.59,3277.82 h55.26
  text "2" at 8291.32,3163.47 h60
  text "23.62mil (0.600mm)" at 8623.14,3163.47 h60
  text "PTH" at 9259.24,3163.47 h60
  text "Slot" at 9518.24,3163.47 h60
  text "2" at 8291.32,3039.14 h60
  text "27.56mil (0.700mm)" at 8623.14,3039.14 h60
  text "PTH" at 9259.24,3039.14 h60
  text "Slot" at 9518.24,3039.14 h60
  text "1" at 8291.32,2914.8 h60
  text "39.37mil (1.000mm)" at 8623.14,2914.8 h60
  text "PTH" at 9259.24,2914.8 h60
  text "Slot" at 9518.24,2914.8 h60
  text "1" at 8291.32,2790.47 h60
  text "39.37mil (1.000mm)" at 8623.14,2790.47 h60
  text "PTH" at 9259.24,2790.47 h60
  text "Slot" at 9518.24,2790.47 h60
  text "1140 Total" at 8291.32,2666.13 h60
  text "Slot definitions :" at 7990.88,2579.1 h60
  text "Routed Path Length" at 8441.36,2579.1 h60
  text "= Calculated from tool start centre position to tool end centre position." at 8980.91,2579.1 h60
  text "Hole Length" at 8441.36,2529.36 h60
  text "= Routed Path Length + Tool Size = Slot length as defined in the PCB layout" at 8781.17,2529.36 h60
  text ".Layer_Name" at 577,-867.49 h60
M17 Embedded Cavity:
  text ".Layer_Name" at 680,-867.49 h60
M18 Embedded Assembly:
  text ".Layer_Name" at 680,-867.49 h60
M19 Embedded Keepout:
  text ".Layer_Name" at 680,-867.49 h60

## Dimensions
0,-409 to 1000,-409 on M2 Board Dimensions
100,0 to 100,4060 on M2 Board Dimensions
0,100 to 3620,100 on M2 Board Dimensions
